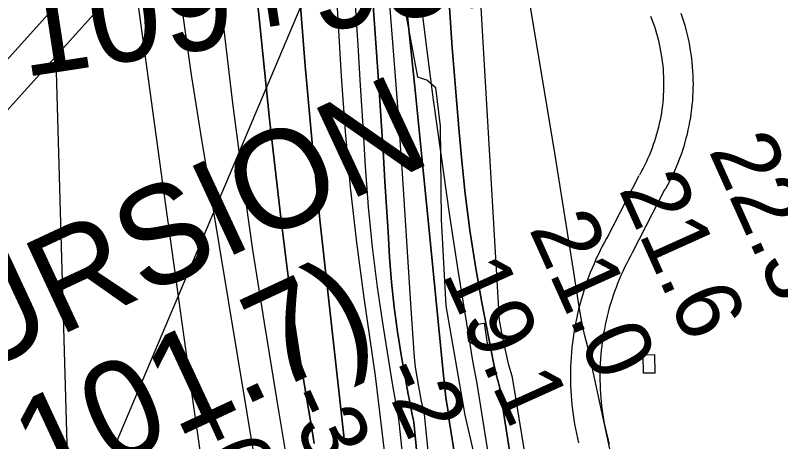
# Model space of a CAD drawing. Extents: x 3625074 to 3663148, y 511451 to 537151.
# Drawn here: x 3659909 to 3660691, y 518899 to 519334 of the extents above; entities that cross this region are included whole.
import ezdxf

# ---------------------------------------------------------------- set-up
doc = ezdxf.new("R2010")
doc.units = 0
for name, color, linetype in [('V-BLDG-OTLN', 7, 'Continuous'), ('V-CHAN-NAID', 7, 'Continuous'), ('V-RIVR-EDGE', 7, 'Continuous'), ('V-RIVR-RANG', 7, 'Continuous'), ('V-ROAD-CNTR', 7, 'Continuous'), ('V-SURV-IDEN', 7, 'Continuous'), ('V-TOPO-DPTH', 7, 'Continuous'), ('V-TOPO-MAJR', 7, 'Continuous'), ('V-TOPO-MINR', 7, 'Continuous'), ('V-TOPO-WATR', 7, 'Continuous'), ('V-UTIL-LINE', 7, 'Continuous')]:
    doc.layers.add(name, color=color, linetype=linetype)

msp = doc.modelspace()

# ---------------------------------------------------------------- linework, layer by layer
at = {"layer": 'V-BLDG-OTLN'}
for points in [[(3660391.45, 518997.2), (3660381.17, 518995.76), (3660372.64, 519001.31), (3660371.2, 519011.04), (3660377.8, 519018.47), (3660388.24, 519020.1)], [(3660562.13, 518988), (3660562.33, 518969.13), (3660550.74, 518969), (3660550.53, 518987.88)]]:
    msp.add_lwpolyline(points, close=True, dxfattribs=at)
at = {"layer": 'V-RIVR-EDGE'}
msp.add_lwpolyline([(3660395.9, 518808.95), (3660368.61, 518926.04), (3660349.28, 519037.61), (3660344.6, 519125.85), (3660343.61, 519220.83), (3660338.8, 519260.05), (3660329.63, 519268.04), (3660320.45, 519271.13), (3660308.96, 519333.04), (3660309.02, 519356.33), (3660317.66, 519383.26), (3660316.58, 519442.7), (3660303.92, 519525.45), (3660288.92, 519655.39), (3660288.53, 519746.07), (3660281.94, 519805.52), (3660274.04, 519830.66), (3660269.93, 519905.43), (3660263.29, 519944.66)], dxfattribs=at)
at = {"layer": 'V-ROAD-CNTR'}
for points in [[(3660588.96, 519336.21), (3660590.36, 519332.13), (3660591.68, 519328.02), (3660592.91, 519323.88), (3660594.06, 519319.72), (3660595.13, 519315.54), (3660596.12, 519311.33), (3660597.02, 519307.11), (3660597.83, 519302.87), (3660598.57, 519298.62), (3660599.21, 519294.35), (3660599.78, 519290.07), (3660600.25, 519285.78), (3660600.65, 519281.48), (3660600.95, 519277.17), (3660601.17, 519272.86), (3660601.31, 519268.55), (3660601.35, 519264.23), (3660601.32, 519259.91), (3660601.19, 519255.6), (3660600.98, 519251.28), (3660600.69, 519246.98), (3660600.31, 519242.68), (3660599.84, 519238.38), (3660599.29, 519234.11), (3660598.65, 519229.84), (3660597.93, 519225.58), (3660597.12, 519221.34), (3660596.24, 519217.11), (3660595.26, 519212.91), (3660594.2, 519208.72), (3660593.06, 519204.56), (3660591.84, 519200.42), (3660590.53, 519196.3), (3660589.15, 519192.21), (3660587.68, 519188.15), (3660586.13, 519184.13), (3660584.5, 519180.13), (3660582.79, 519176.16), (3660581, 519172.23), (3660579.14, 519168.34), (3660577.2, 519164.48), (3660575.18, 519160.67), (3660573.11, 519156.94), (3660572.79, 519156.38)], [(3660558, 519333.32), (3660559.4, 519329.71), (3660560.67, 519326.22), (3660561.88, 519322.7), (3660563.01, 519319.15), (3660564.08, 519315.59), (3660565.07, 519312), (3660565.99, 519308.4), (3660566.84, 519304.78), (3660567.62, 519301.14), (3660568.32, 519297.49), (3660568.95, 519293.82), (3660569.51, 519290.14), (3660569.99, 519286.46), (3660570.4, 519282.76), (3660570.74, 519279.05), (3660571, 519275.34), (3660571.2, 519271.63), (3660571.31, 519267.91), (3660571.35, 519264.19), (3660571.32, 519260.47), (3660571.21, 519256.75), (3660571.03, 519253.04), (3660570.78, 519249.33), (3660570.45, 519245.62), (3660570.05, 519241.92), (3660569.57, 519238.23), (3660569.03, 519234.55), (3660568.4, 519230.89), (3660567.71, 519227.23), (3660566.94, 519223.59), (3660566.1, 519219.97), (3660565.19, 519216.36), (3660564.21, 519212.77), (3660563.15, 519209.21), (3660562.03, 519205.66), (3660560.83, 519202.14), (3660559.57, 519198.64), (3660558.23, 519195.17), (3660556.83, 519191.72), (3660555.36, 519188.31), (3660553.82, 519184.92), (3660552.21, 519181.57), (3660550.54, 519178.24), (3660548.8, 519174.96), (3660546.97, 519171.65), (3660546.73, 519171.24)], [(3660513.21, 519106.56), (3660546.44, 519170.71)], [(3660539.85, 519092.77), (3660573.08, 519156.91)], [(3660513.42, 519106.95), (3660511.1, 519102.76), (3660508.78, 519098.42), (3660506.54, 519094.05), (3660504.38, 519089.63), (3660502.29, 519085.18), (3660500.28, 519080.69), (3660498.35, 519076.17), (3660496.5, 519071.62), (3660494.72, 519067.04), (3660493.02, 519062.42), (3660491.4, 519057.78), (3660489.87, 519053.11), (3660488.41, 519048.41), (3660487.03, 519043.69), (3660485.73, 519038.95), (3660484.52, 519034.19), (3660483.39, 519029.4), (3660482.34, 519024.6), (3660481.37, 519019.78), (3660480.49, 519014.94), (3660479.69, 519010.09), (3660478.97, 519005.23), (3660478.33, 519000.35), (3660477.79, 518995.47), (3660477.32, 518990.57), (3660476.94, 518985.67), (3660476.64, 518980.76), (3660476.43, 518975.85), (3660476.3, 518970.94), (3660476.25, 518966.02), (3660476.29, 518961.1), (3660476.42, 518956.19), (3660476.62, 518951.28), (3660476.92, 518946.37), (3660477.29, 518941.47), (3660477.75, 518936.57), (3660478.3, 518931.68), (3660478.93, 518926.81), (3660479.64, 518921.94), (3660480.44, 518917.09), (3660481.32, 518912.26), (3660482.28, 518907.43), (3660483.32, 518902.63), (3660484.45, 518897.84)], [(3660539.65, 519092.38), (3660537.45, 519088.42), (3660535.37, 519084.54), (3660533.37, 519080.62), (3660531.43, 519076.67), (3660529.57, 519072.68), (3660527.77, 519068.66), (3660526.04, 519064.62), (3660524.38, 519060.54), (3660522.78, 519056.44), (3660521.27, 519052.3), (3660519.82, 519048.15), (3660518.44, 519043.97), (3660517.13, 519039.77), (3660515.9, 519035.54), (3660514.74, 519031.29), (3660513.66, 519027.03), (3660512.64, 519022.74), (3660511.7, 519018.45), (3660510.84, 519014.13), (3660510.04, 519009.8), (3660509.33, 519005.46), (3660508.69, 519001.1), (3660508.12, 518996.74), (3660507.62, 518992.37), (3660507.21, 518987.98), (3660506.87, 518983.6), (3660506.6, 518979.2), (3660506.41, 518974.8), (3660506.29, 518970.4), (3660506.25, 518966.01), (3660506.29, 518961.6), (3660506.4, 518957.2), (3660506.59, 518952.81), (3660506.85, 518948.41), (3660507.19, 518944.02), (3660507.6, 518939.64), (3660508.09, 518935.27), (3660508.65, 518930.9), (3660509.29, 518926.55), (3660510, 518922.2), (3660510.79, 518917.87), (3660511.65, 518913.56), (3660512.58, 518909.26), (3660513.59, 518904.97), (3660514.68, 518900.71), (3660515.83, 518896.46)]]:
    msp.add_lwpolyline(points, dxfattribs=at)
at = {"layer": 'V-TOPO-DPTH'}
for points in [[(3660186.94, 520103.09), (3660186.77, 519693.19), (3660186.73, 519681.74), (3660186.65, 519670.29), (3660186.51, 519658.84), (3660186.32, 519647.39), (3660186.14, 519637.84), (3660186.02, 519631.17), (3660185.91, 519624.49), (3660185.81, 519617.82), (3660185.73, 519611.14), (3660185.63, 519602.55), (3660185.66, 519597.8), (3660185.73, 519595.42), (3660185.84, 519593.05), (3660194.33, 519440.12), (3660199.36, 519361.34), (3660205.24, 519282.63), (3660212.41, 519204.02), (3660220.44, 519125.49), (3660244.82, 518904.98), (3660245.25, 518901.27), (3660245.73, 518897.56)], [(3660186.94, 520103.09), (3660186.77, 519693.19), (3660186.73, 519681.74), (3660186.65, 519670.29), (3660186.51, 519658.84), (3660186.32, 519647.39), (3660186.14, 519637.84), (3660186.02, 519631.17), (3660185.91, 519624.49), (3660185.81, 519617.82), (3660185.73, 519611.14), (3660185.63, 519602.55), (3660185.66, 519597.8), (3660185.73, 519595.42), (3660185.84, 519593.05), (3660194.33, 519440.12), (3660199.36, 519361.34), (3660205.24, 519282.63), (3660212.41, 519204.02), (3660220.44, 519125.49), (3660244.82, 518904.98), (3660245.25, 518901.27), (3660245.73, 518897.56)], [(3660268.04, 519977.3), (3660272.91, 519748.37), (3660273.54, 519725.92), (3660274.36, 519703.47), (3660275.47, 519681.03), (3660276.79, 519658.61), (3660279.1, 519623.03), (3660279.43, 519618.4), (3660279.8, 519613.78), (3660280.23, 519609.16), (3660280.7, 519604.54), (3660301.15, 519414.38), (3660309.46, 519336.07), (3660317.62, 519257.74), (3660325.56, 519179.4), (3660333.36, 519101.03), (3660346.22, 518969.94), (3660347.6, 518957.13), (3660349.14, 518944.34), (3660350.91, 518931.58), (3660352.84, 518918.84), (3660486.82, 518079.66)], [(3660486.82, 518079.66), (3660352.84, 518918.84), (3660350.91, 518931.58), (3660349.14, 518944.34), (3660347.6, 518957.13), (3660346.22, 518969.94), (3660333.36, 519101.03), (3660325.56, 519179.4), (3660317.62, 519257.74), (3660309.46, 519336.07), (3660301.15, 519414.38), (3660280.7, 519604.54), (3660280.23, 519609.16), (3660279.8, 519613.78), (3660279.43, 519618.4), (3660279.1, 519623.03), (3660276.79, 519658.61), (3660275.47, 519681.03), (3660274.36, 519703.47), (3660273.54, 519725.92), (3660272.91, 519748.37), (3660268.04, 519977.3)], [(3660391.13, 518016.01), (3660277.16, 518966.49), (3660265.58, 519046.02), (3660258.12, 519102.37), (3660251.62, 519158.81), (3660246.57, 519215.4), (3660242.5, 519272.09), (3660239.06, 519330.28), (3660237.4, 519357.95), (3660235.71, 519385.62), (3660233.97, 519413.28), (3660232.2, 519440.94), (3660232.11, 519442.38), (3660230.4, 519469.32), (3660228.73, 519496.27), (3660227.15, 519523.22), (3660225.61, 519550.17), (3660224.26, 519577.13), (3660223.11, 519604.1), (3660222.27, 519631.08), (3660221.63, 519658.06), (3660218.02, 519859.35), (3660216.33, 519955.82)], [(3660391.13, 518016.01), (3660277.16, 518966.49), (3660265.58, 519046.02), (3660258.12, 519102.37), (3660251.62, 519158.81), (3660246.57, 519215.4), (3660242.5, 519272.09), (3660239.06, 519330.28), (3660237.4, 519357.95), (3660235.71, 519385.62), (3660233.97, 519413.28), (3660232.2, 519440.94), (3660232.11, 519442.38), (3660230.4, 519469.32), (3660228.73, 519496.27), (3660227.15, 519523.22), (3660225.61, 519550.17), (3660224.26, 519577.13), (3660223.11, 519604.1), (3660222.27, 519631.08), (3660221.63, 519658.06), (3660218.02, 519859.35), (3660216.33, 519955.82)], [(3660272.46, 519378.2), (3660276.53, 519320.35), (3660280.45, 519262.48), (3660285.21, 519190), (3660286.87, 519164.39), (3660288.5, 519138.77), (3660290.09, 519113.15), (3660291.64, 519087.52), (3660293.63, 519061.95), (3660296.22, 519036.46), (3660299.71, 519011.07), (3660303.8, 518985.75), (3660310.65, 518947.72), (3660312.46, 518938.17), (3660314.38, 518928.64), (3660316.47, 518919.15), (3660403.95, 518019.13)], [(3660403.95, 518019.13), (3660316.47, 518919.15), (3660314.38, 518928.64), (3660312.46, 518938.17), (3660310.65, 518947.72), (3660303.8, 518985.75), (3660299.71, 519011.07), (3660296.22, 519036.46), (3660293.63, 519061.95), (3660291.64, 519087.52), (3660290.09, 519113.15), (3660288.5, 519138.77), (3660286.87, 519164.39), (3660285.21, 519190), (3660280.45, 519262.48), (3660276.53, 519320.35), (3660272.46, 519378.2)], [(3660214.73, 518897.42), (3660212.48, 518910.31), (3660204.95, 518954.45), (3660199.23, 518989.45), (3660193.87, 519024.51), (3660189.03, 519059.64), (3660184.53, 519094.82), (3660180.55, 519127.87), (3660174.69, 519177.91), (3660169.05, 519227.98), (3660163.73, 519278.08), (3660158.63, 519328.2), (3660156.71, 519347.71)], [(3660156.71, 519347.71), (3660158.63, 519328.2), (3660163.73, 519278.08), (3660169.05, 519227.98), (3660174.69, 519177.91), (3660180.55, 519127.87), (3660184.53, 519094.82), (3660189.03, 519059.64), (3660193.87, 519024.51), (3660199.23, 518989.45), (3660204.95, 518954.45), (3660212.48, 518910.31), (3660214.73, 518897.42)], [(3660352.82, 519341.96), (3660355.62, 519300.95), (3660358.83, 519259.97), (3660362.3, 519219.01), (3660364.98, 519189.11), (3660368.88, 519151.91), (3660373.53, 519114.8), (3660379.28, 519077.85), (3660385.78, 519041.01), (3660395.14, 518992.25), (3660397.71, 518979.91), (3660400.54, 518967.63), (3660403.74, 518955.45), (3660519.46, 518215.36)]]:
    msp.add_lwpolyline(points, dxfattribs=at)
at = {"layer": 'V-TOPO-MAJR'}
msp.add_lwpolyline([(3660188.38, 518871.51), (3660183.5, 518899.99), (3660178.75, 518928.5), (3660163.73, 519020.43), (3660152.12, 519094.99), (3660141.26, 519169.66), (3660131.52, 519244.48), (3660122.54, 519319.41), (3660094.98, 519564.85), (3660094.78, 519566.68), (3660094.41, 519570.33), (3660094.2, 519572.62), (3660093.93, 519577.42), (3660093.95, 519582.23), (3660094.01, 519583.83), (3660094.11, 519585.43), (3660107.96, 519792.08), (3660114.36, 519897.04), (3660119.9, 520002.04)], dxfattribs=at)
at = {"layer": 'V-TOPO-MINR'}
for points in [[(3660245.73, 518897.56), (3660245.25, 518901.27), (3660244.82, 518904.98), (3660220.44, 519125.49), (3660212.41, 519204.02), (3660205.24, 519282.63), (3660199.36, 519361.34), (3660194.33, 519440.12), (3660185.84, 519593.05), (3660185.73, 519595.42), (3660185.66, 519597.8), (3660185.63, 519602.55), (3660185.73, 519611.14), (3660185.81, 519617.82), (3660185.91, 519624.49), (3660186.02, 519631.17), (3660186.14, 519637.84), (3660186.32, 519647.39), (3660186.51, 519658.84), (3660186.65, 519670.29), (3660186.73, 519681.74), (3660186.77, 519693.19), (3660186.94, 520103.09)], [(3660492.57, 518257.69), (3660381, 518958.66), (3660376.64, 518981.76), (3660372.67, 519004.95), (3660361.74, 519074.13), (3660352.89, 519132), (3660344.41, 519189.93), (3660336.51, 519247.94), (3660328.98, 519306), (3660293.52, 519590.62), (3660293.14, 519593.68), (3660292.76, 519596.74), (3660292.38, 519599.8), (3660292, 519602.86), (3660291.65, 519605.65), (3660291.47, 519607.32), (3660291.23, 519610.67), (3660291.17, 519612.34), (3660291.12, 519615.7), (3660291.11, 519617.38), (3660291.1, 519619.06), (3660290.96, 520074.14)], [(3660806.67, 517551.77), (3660493.86, 518995.4), (3660490.53, 519008.34), (3660487.8, 519021.43), (3660485.46, 519034.6), (3660479.67, 519072.1), (3660474.68, 519104.08), (3660469.61, 519136.05), (3660464.42, 519168.01), (3660459.16, 519199.95), (3660387.17, 519631.68), (3660387.15, 519631.84), (3660386.94, 519634), (3660386.74, 519638.01), (3660386.66, 519643.42), (3660386.64, 519647.12), (3660386.65, 519650.83), (3660386.72, 519654.54), (3660386.83, 519658.24), (3660401.11, 520041.08)], [(3660391.13, 518016.01), (3660277.16, 518966.49), (3660265.58, 519046.02), (3660258.12, 519102.37), (3660251.62, 519158.81), (3660246.57, 519215.4), (3660242.5, 519272.09), (3660239.06, 519330.28), (3660237.4, 519357.95), (3660235.71, 519385.62), (3660233.97, 519413.28), (3660232.2, 519440.94), (3660232.11, 519442.38), (3660230.4, 519469.32), (3660228.73, 519496.27), (3660227.15, 519523.22), (3660225.61, 519550.17), (3660224.26, 519577.13), (3660223.11, 519604.1), (3660222.27, 519631.08), (3660221.63, 519658.06), (3660218.02, 519859.35), (3660216.33, 519955.82)], [(3660099.73, 518878.17), (3660090.02, 518946.89), (3660082.1, 519003.24), (3660074.23, 519059.59), (3660066.42, 519115.95), (3660058.66, 519172.32), (3660030.69, 519376.34), (3660027.39, 519400.13), (3660024.04, 519423.91), (3660020.62, 519447.68), (3660017.15, 519471.44), (3660013.69, 519494.93), (3660012.05, 519506.96), (3660010.59, 519519.01), (3660009.39, 519531.08), (3660008.37, 519543.18), (3660007.72, 519555.29), (3660007.41, 519567.41), (3660007.58, 519579.53), (3660008.08, 519591.65), (3660022.21, 519821.55), (3660026.68, 519884.88), (3660031.93, 519948.13)], [(3660417.12, 518964.58), (3660415.63, 518969.24), (3660414.24, 518973.93), (3660413.02, 518978.66), (3660411.9, 518983.42), (3660406.92, 519006.57), (3660403.76, 519022.98), (3660369.47, 519608.34), (3660368.45, 519618.5), (3660367.5, 519628.66), (3660366.67, 519638.83), (3660365.91, 519649.01), (3660360.29, 519730.3), (3660357.15, 519781.14), (3660354.48, 519832.01), (3660352.54, 519882.9), (3660351.09, 519933.82)], [(3660155.77, 518870.94), (3660098.73, 519213.39), (3660089.37, 519273.5), (3660080.87, 519333.72), (3660073.65, 519394.1), (3660067.28, 519454.6), (3660059.24, 519539.56), (3660057.87, 519557.67), (3660056.95, 519575.8), (3660056.72, 519593.95), (3660056.93, 519612.11), (3660059.41, 519693.46), (3660060.84, 519727.33), (3660062.79, 519761.15), (3660065.52, 519794.92), (3660068.78, 519828.66), (3660072.27, 519862.38), (3660075.56, 519896.13), (3660078.53, 519929.9)], [(3659965.42, 518789.86), (3659944.89, 519502.14), (3659942.94, 519529.1), (3659941.86, 519556.08), (3659942.08, 519583.08), (3659943.16, 519610.09), (3659949.59, 519709.96), (3659952.55, 519751.43), (3659955.88, 519792.87), (3659959.79, 519834.26), (3659964.09, 519875.62), (3659968.64, 519916.96)], [(3660418.73, 518011.66), (3660327.32, 518927.2), (3660326.49, 518930.5), (3660325.69, 518933.82), (3660324.96, 518937.15), (3660324.28, 518940.48), (3660321.3, 518955.6), (3660319.58, 518965.39), (3660318.13, 518975.21), (3660317.06, 518985.09), (3660316.27, 518994.99), (3660315.66, 519004.93), (3660315.04, 519014.86), (3660314.4, 519024.79), (3660313.76, 519034.72), (3660304.64, 519172.63), (3660299.52, 519245.9), (3660294.02, 519319.15), (3660287.96, 519392.34)], [(3660403.95, 518019.13), (3660316.47, 518919.15), (3660314.38, 518928.64), (3660312.46, 518938.17), (3660310.65, 518947.72), (3660303.8, 518985.75), (3660299.71, 519011.07), (3660296.22, 519036.46), (3660293.63, 519061.95), (3660291.64, 519087.52), (3660290.09, 519113.15), (3660288.5, 519138.77), (3660286.87, 519164.39), (3660285.21, 519190), (3660280.45, 519262.48), (3660276.53, 519320.35), (3660272.46, 519378.2)], [(3660214.73, 518897.42), (3660212.48, 518910.31), (3660204.95, 518954.45), (3660199.23, 518989.45), (3660193.87, 519024.51), (3660189.03, 519059.64), (3660184.53, 519094.82), (3660180.55, 519127.87), (3660174.69, 519177.91), (3660169.05, 519227.98), (3660163.73, 519278.08), (3660158.63, 519328.2), (3660156.71, 519347.71)], [(3660396.34, 518021.6), (3660300.96, 518922.5), (3660297.85, 518939.41), (3660294.94, 518956.36), (3660285.24, 519015.88), (3660279.23, 519056.72), (3660274.05, 519097.66), (3660270.13, 519138.73), (3660267.05, 519179.89), (3660264.56, 519221.13), (3660262.03, 519262.36), (3660259.42, 519303.58), (3660256.76, 519344.8)], [(3660519.46, 518215.36), (3660403.74, 518955.45), (3660400.54, 518967.63), (3660397.71, 518979.91), (3660395.14, 518992.25), (3660385.78, 519041.01), (3660379.28, 519077.85), (3660373.53, 519114.8), (3660368.88, 519151.91), (3660364.98, 519189.11), (3660362.3, 519219.01), (3660358.83, 519259.97), (3660355.62, 519300.95), (3660352.82, 519341.96)], [(3660725.96, 517547.35), (3660563.69, 518123.34), (3660560.94, 518127.69), (3660558.48, 518132.17), (3660556.45, 518136.87), (3660554.72, 518141.7), (3660546.24, 518169.31), (3660545.5, 518172.25), (3660544.95, 518175.23), (3660544.7, 518178.24), (3660544.65, 518181.28), (3660544.92, 518184.3), (3660417.12, 518964.58)]]:
    msp.add_lwpolyline(points, dxfattribs=at)
at = {"layer": 'V-TOPO-WATR'}
msp.add_lwpolyline([(3660486.82, 518079.66), (3660352.84, 518918.84), (3660350.91, 518931.58), (3660349.14, 518944.34), (3660347.6, 518957.13), (3660346.22, 518969.94), (3660333.36, 519101.03), (3660325.56, 519179.4), (3660317.62, 519257.74), (3660309.46, 519336.07), (3660301.15, 519414.38), (3660280.7, 519604.54), (3660280.23, 519609.16), (3660279.8, 519613.78), (3660279.43, 519618.4), (3660279.1, 519623.03), (3660276.79, 519658.61), (3660275.47, 519681.03), (3660274.36, 519703.47), (3660273.54, 519725.92), (3660272.91, 519748.37), (3660268.04, 519977.3)], dxfattribs=at)
at = {"layer": 'V-UTIL-LINE'}
for p, q in [((3658387.56, 517607.48), (3660280.6, 519710.64)), ((3658394.86, 517563.67), (3660287.9, 519666.82)), ((3660309.81, 519601.1), (3659276.96, 517160.86))]:
    msp.add_line(p, q, dxfattribs=at)

# ---------------------------------------------------------------- texts
at = {"layer": 'V-CHAN-NAID'}
for s, p in [('AUDUBON PARK EXCURSION', (3658613.28, 518381.24)), ('BOAT LANDING (101.7)', (3658962.13, 518384.74))]:
    msp.add_text(s, height=100, rotation=24.99942, dxfattribs=at).set_placement(p)
at = {"layer": 'V-RIVR-RANG'}
for s, rotation, p in [('22.3', 294.24833, (3660616.82, 519196.23)), ('21.6', 294.24833, (3660524.98, 519156.62)), ('21.0', 294.24833, (3660433.47, 519116.3)), ('19.1', 294.24833, (3660344.56, 519070.2)), ('-2', 294.52803, (3660279.75, 518969.97)), ('-31', 294.52803, (3660181.99, 518943.32)), ('-63', 294.52803, (3660085.33, 518914.27))]:
    msp.add_text(s, height=67, rotation=rotation, dxfattribs=at).set_placement(p)
at = {"layer": 'V-SURV-IDEN'}
msp.add_text('109+95.7', height=100, rotation=8.74062, dxfattribs=at).set_placement((3659917.42, 519270.71))

doc.saveas('drawing.dxf')
